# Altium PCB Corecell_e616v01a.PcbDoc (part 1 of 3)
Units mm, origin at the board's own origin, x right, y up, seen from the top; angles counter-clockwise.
Board outline 72.95 x 30.9 mm, 4 copper layers (Top Layer, MidLayer1 - GND, MidLayer2, Bottom Layer), stack 0.637 mm thick; 233 components, 174 nets, 666 pads, 1160 vias.
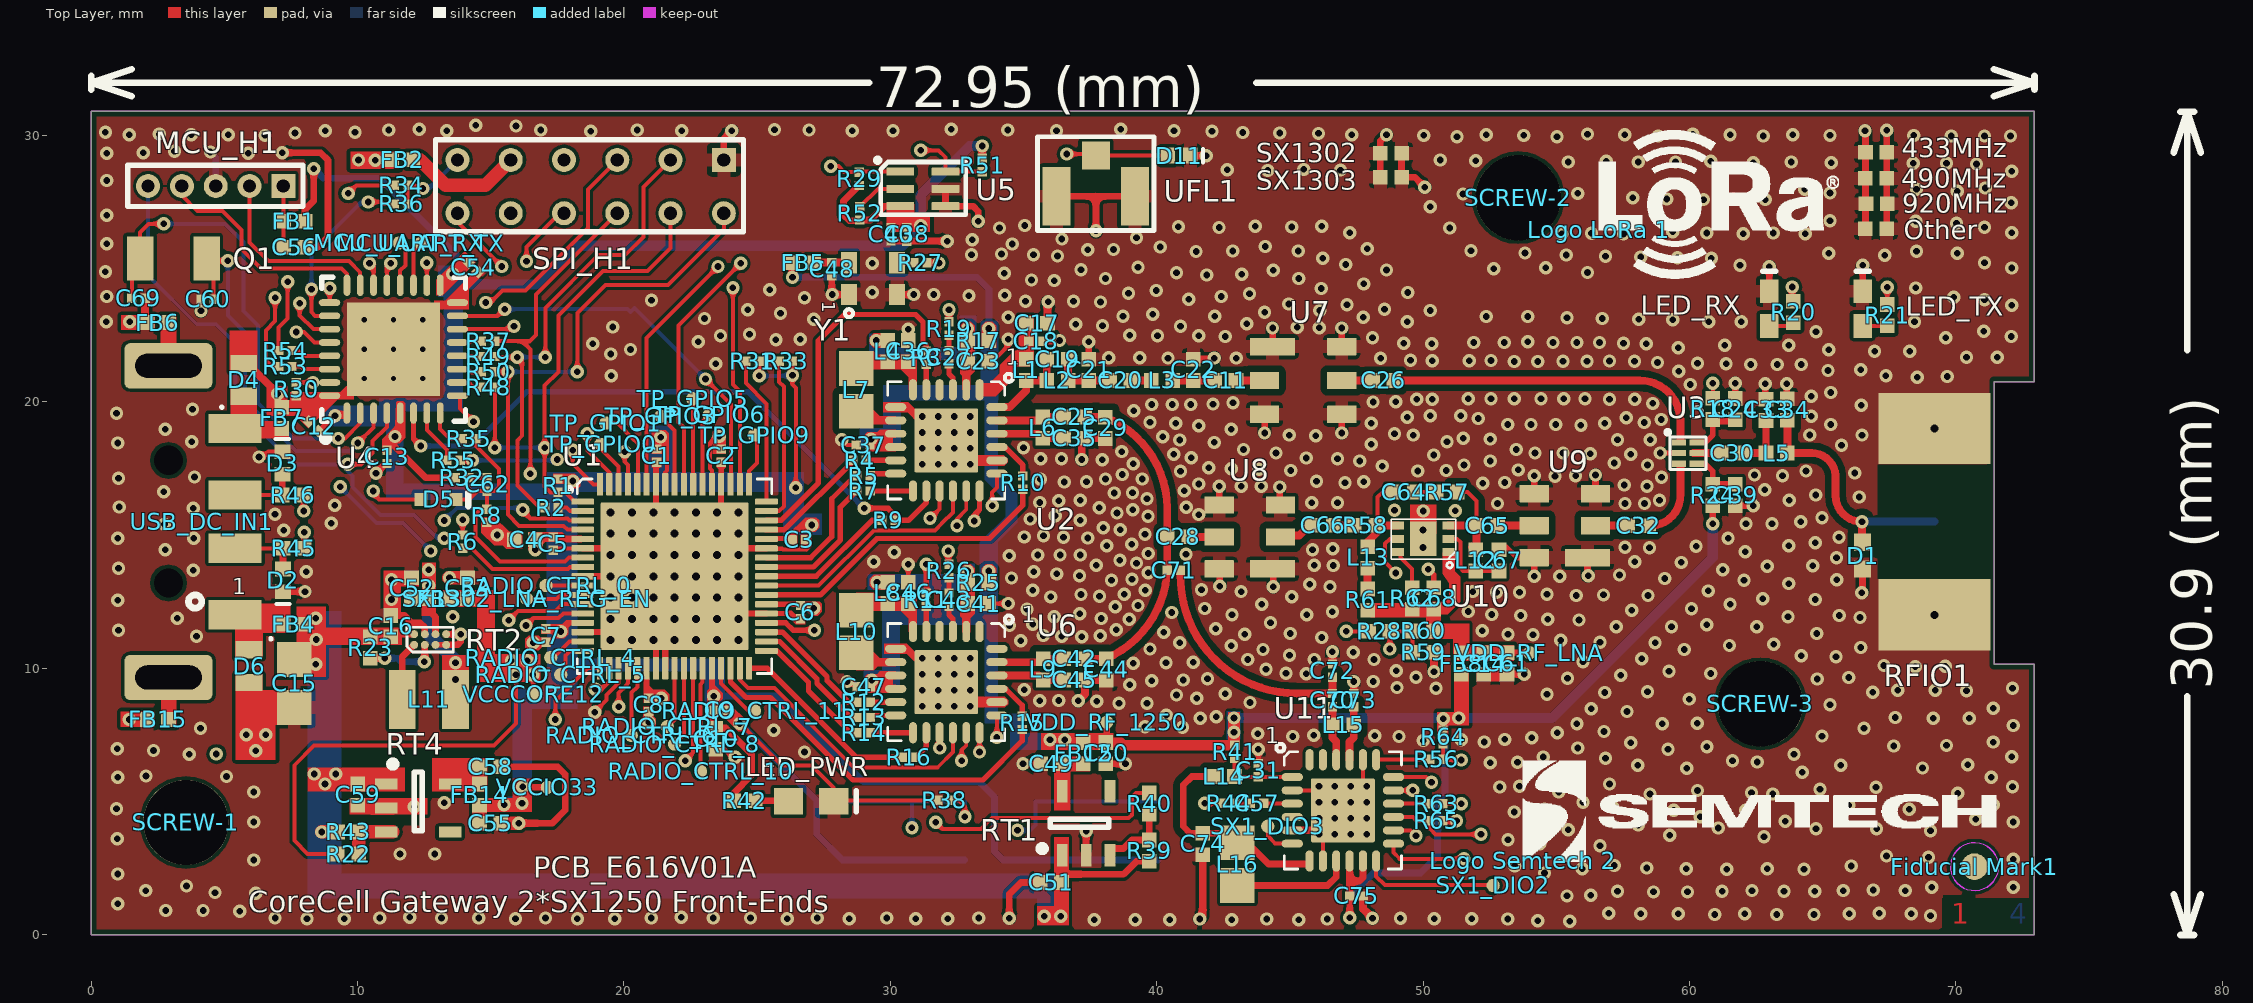
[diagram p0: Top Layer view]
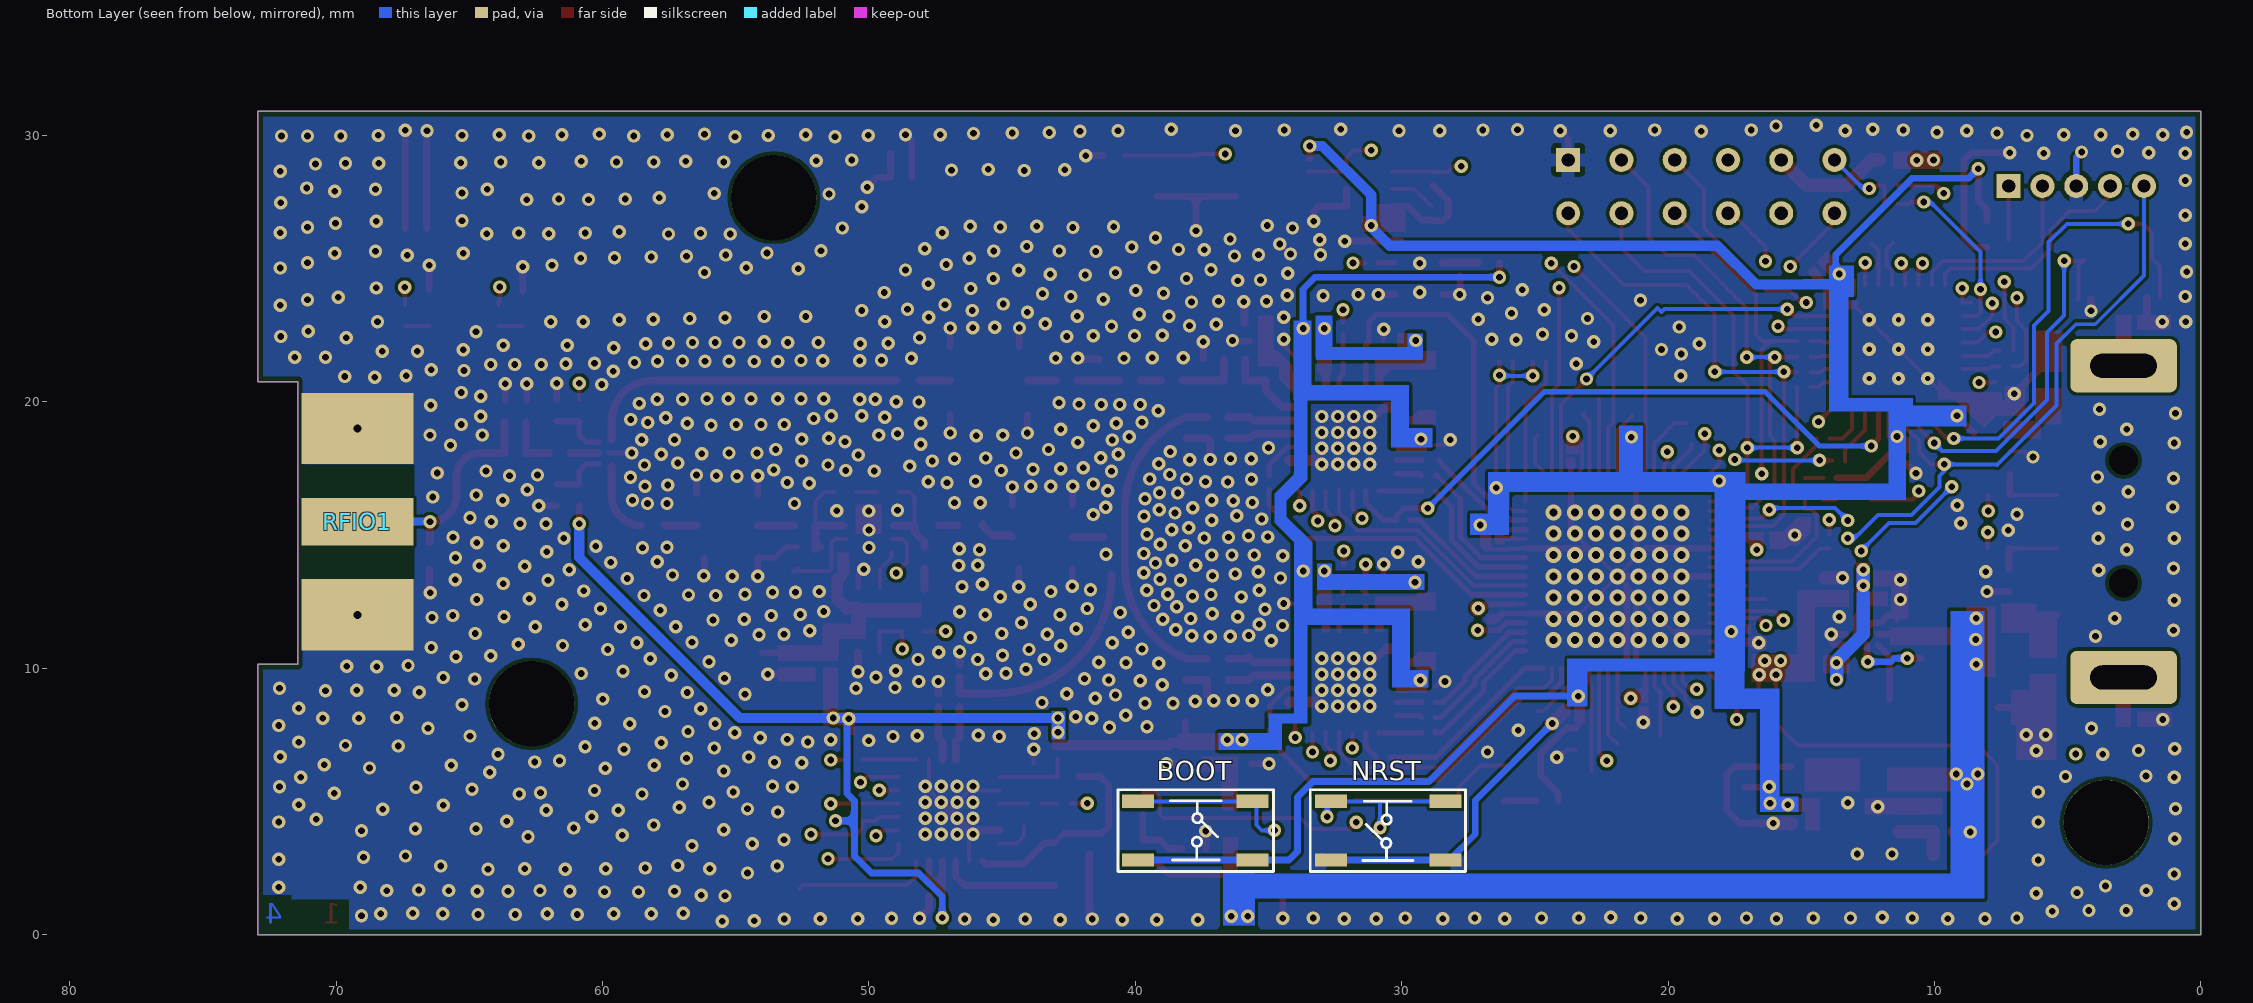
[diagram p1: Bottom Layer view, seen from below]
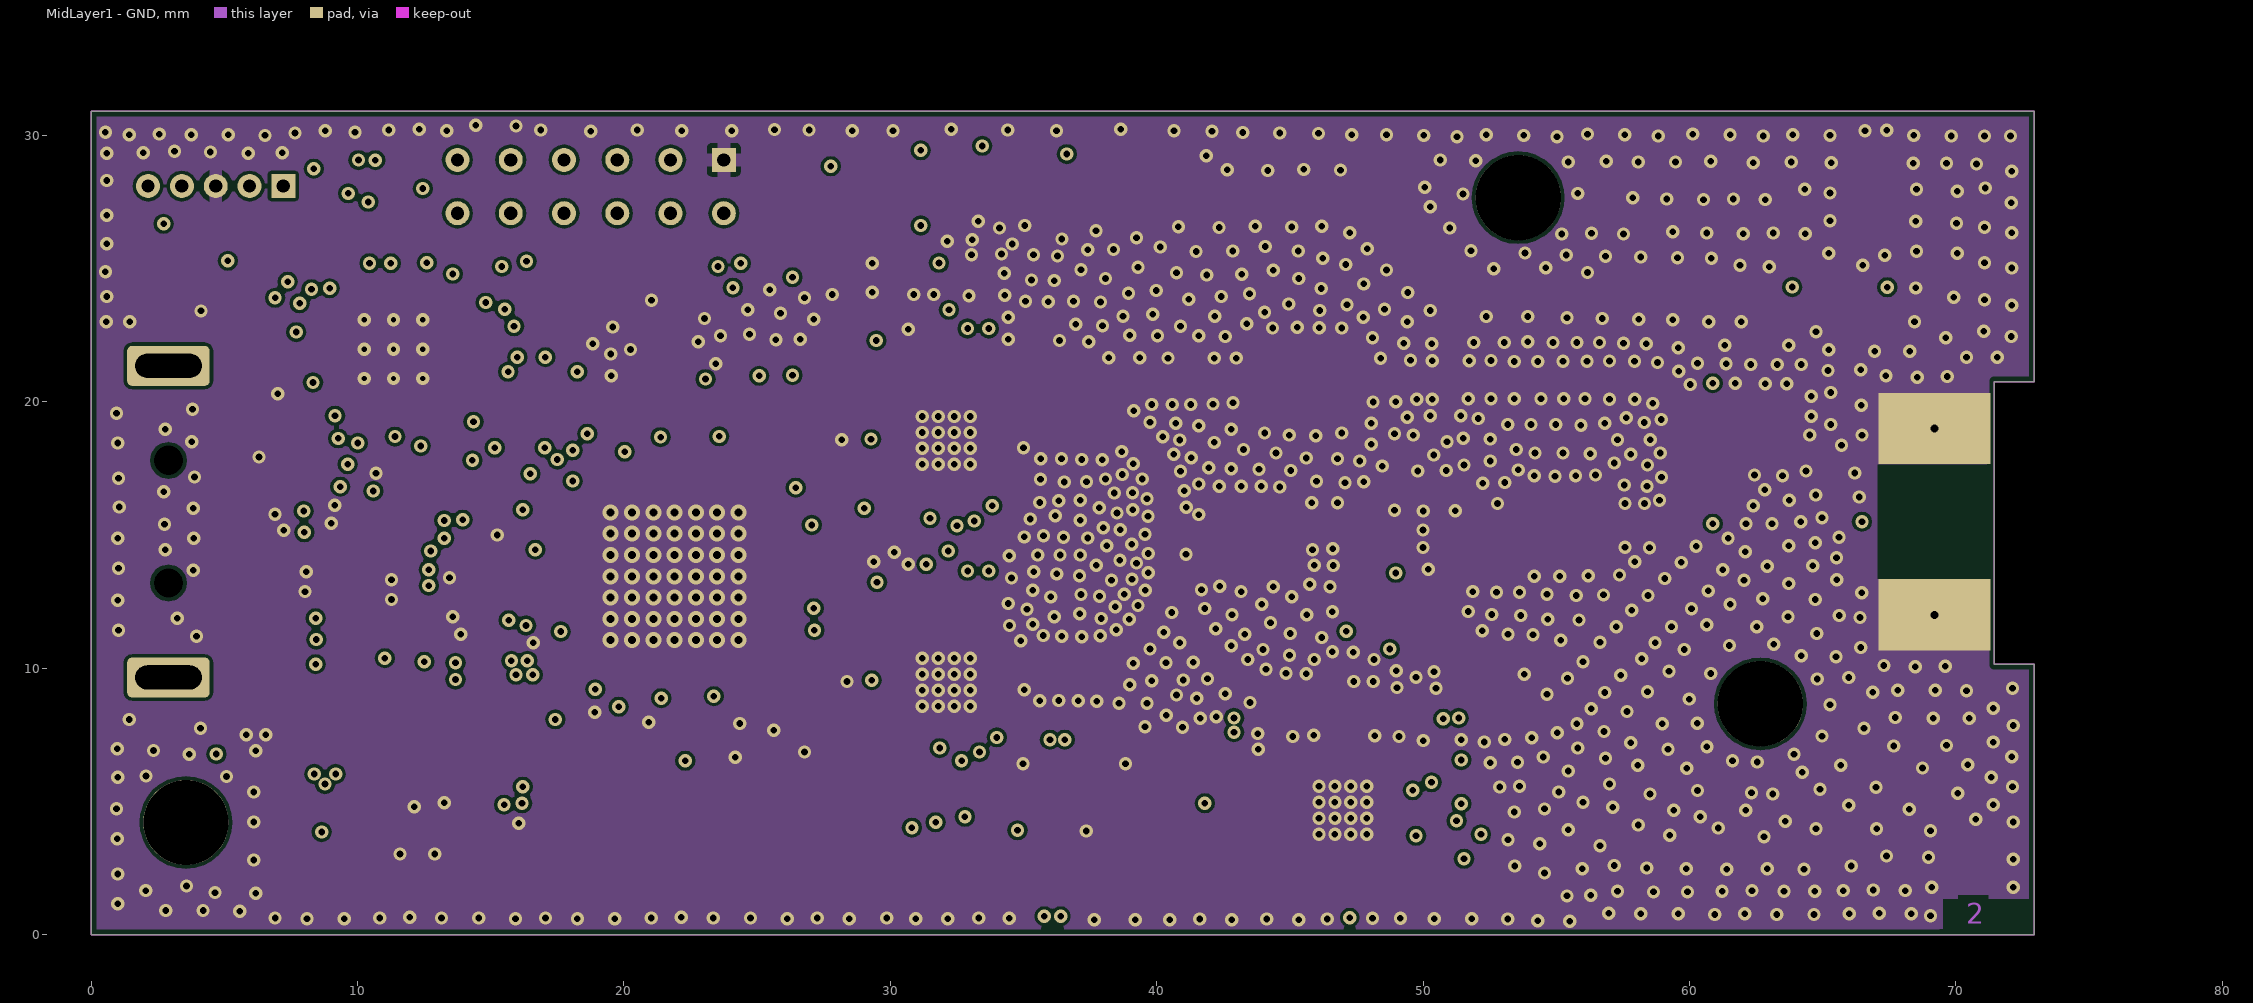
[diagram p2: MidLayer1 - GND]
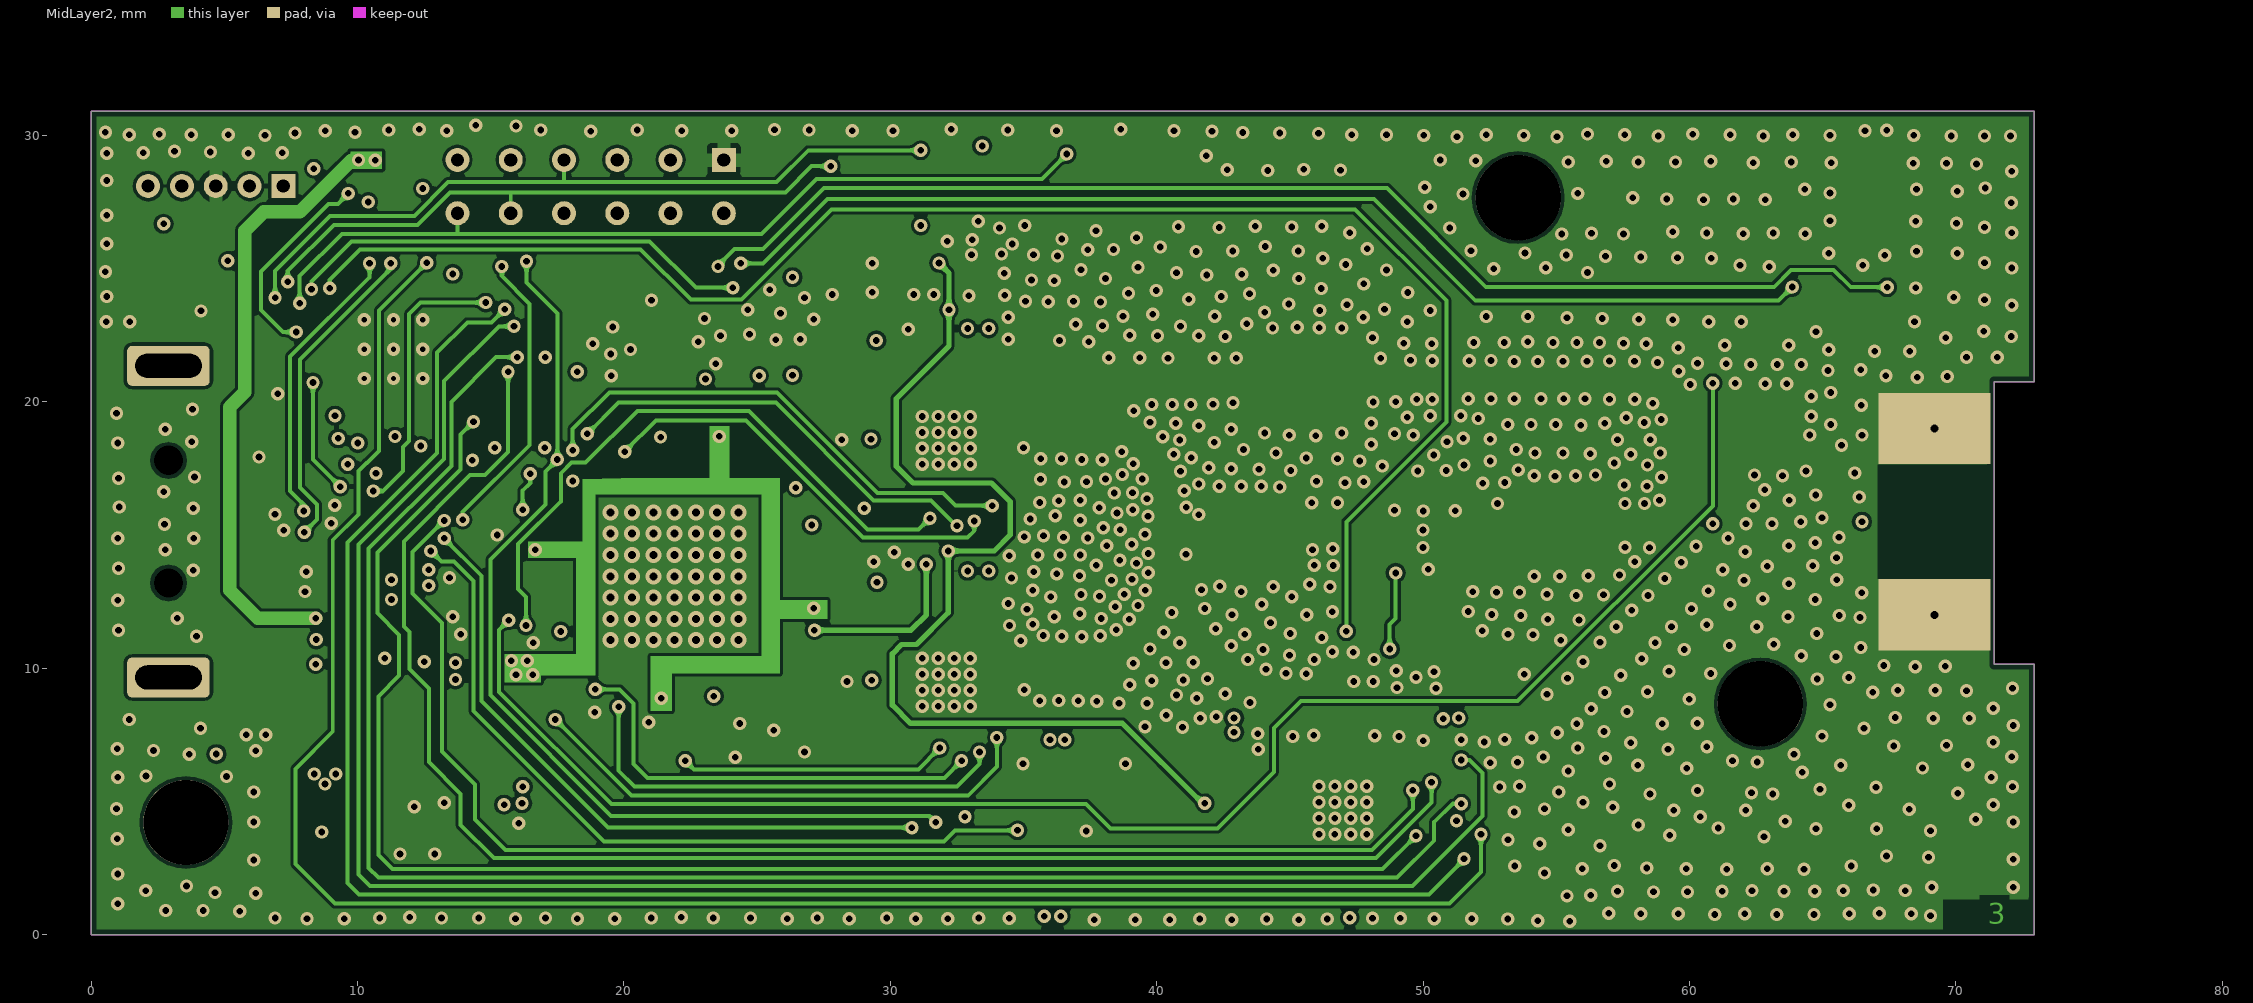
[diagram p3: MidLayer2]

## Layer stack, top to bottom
Top Solder: solder mask 0.0102, Solder Resist, Dk 3.5
Top Layer: signal copper 0.035
Dielectric1: core 0.15, FR-4, Dk 4.3
MidLayer1 - GND: signal copper 0.018
Dielectric 5: prepreg 0.127, Dk 4.2
MidLayer2: signal copper 0.018
Dielectric2: core 0.254, FR-4, Dk 4.2
Bottom Layer: signal copper 0.035
Bottom Solder: solder mask 0.0102, Solder Resist, Dk 3.5

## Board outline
0,0 0,30.9 72.95,30.9 72.95,20.75 71.45,20.75 71.45,10.15 72.95,10.15 72.95,0

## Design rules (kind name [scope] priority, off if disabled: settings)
BoardOutlineClearance [All] p1: gap=0.2 ignorepadtopadclearanceinfootprint=FALSE
Clearance Clearance_RF_Area_TOP [InNet('GND') And OnLayer('Top Layer') And (InPolygon) vs InNet('NetL8*') or InNet('NetC8*')  or  InNet('NetL9*') or InNet('NetC9*') or  InNet('NetL7*') or InNet('NetC7*')  or  InNet('NetU8*') or InNet('NetU9*') or InNet('NetU7*')  or  InNet('NetR8*') or InNet('NetR9*') or  InNet('NetR7*') or InNet('RF*')  or  InNet('NetU10*') or  InNet('NetC28*') or  InNet('NetC66*') or  InNet('NetC58*') or  InNet('NetC65*')   or  InNet('NetC32*') or  InNet('NetU3*') or  InNet('NetC42*') or  InNet('NetC44*')  or  InNet('NetC29*') or  InNet('NetC25*')  or  InNet('NetC30*')  or  InNet('NetL5*')  or  InNet('NetC34*')or  InNet('NetC26*')  or  InNet('NetC11*')   or  InNet('NetL3*') or  InNet('NetC20*')  or  InNet('NetL2*')       or  InNet('NetC19*')] p1: gap=0.25 ignorepadtopadclearanceinfootprint=FALSE except(0.15: Arc-Arc Arc-Track Track-Track)
Clearance Clearance_DC_Supply [((InPolygon) and ( InNet('VCCIO33') or InNet('VCCCORE12') or InNet('VCC_FEM') or InNet('VCC_FEM_1') or InNet('VCC_REG_IN') or  InNet('VDD_RF_125x') or  InNet('VDD_RF_126x') or InNet('VCC5V_IN') or  InNet('VCC5V')))  AND InComponentClass('SX1302_e520v01a_Power&Interface')] p2: gap=0.15 ignorepadtopadclearanceinfootprint=FALSE
Clearance Clearance_GND [InNet('GND')] p3: gap=0.12 ignorepadtopadclearanceinfootprint=FALSE
Clearance "Clearance ALL" [All] p4: gap=0.12 ignorepadtopadclearanceinfootprint=FALSE
ComponentClearance "Component Test Pin" [HasFootprint('PIN_SMD')] p1: gap=0.05 collisioncheckmode=3 verticalgap=0.2 showdistances=FALSE
ComponentClearance [All] p2: gap=0.2 collisioncheckmode=3 verticalgap=0.25 showdistances=FALSE
ComponentOrientations [All] p1: allowedrotations=32
DiffPairsRouting [All] p1: maxlimit=0.3 minlimit=0.15 mostfreqgap=0.2 toplayer_minwidth=0.15 toplayer_maxwidth=0.3 toplayer_prefwidth=0.2 midlayer1_minwidth=0.15 midlayer1_maxwidth=0.3 midlayer1_prefwidth=0.2 midlayer2_minwidth=0.15 midlayer2_maxwidth=0.3 midlayer2_prefwidth=0.2 bottomlayer_minwidth=0.15 bottomlayer_maxwidth=0.3 bottomlayer_prefwidth=0.2 maxuncoupledlength=12.7
HoleSize [All] p1: absolutevalues=TRUE maxlimit=6.5 minlimit=0.2 maxpercent=80.000 minpercent=20.000
HoleToHoleClearance [All] p1: gap=0.2 allowstackedmicrovias=TRUE
Length [All] p1: maxlimit=400 minlimit=0
MinimumAnnularRing [All] p1: minimumring=0.1
MinimumSolderMaskSliver [All] p1: minsoldermaskwidth=0.05
NetsToIgnore [All] p1:
OvershootFalling [All] p1: maximum=1.000
PermittedLayers [All] p1: toplayerpermitted=TRUE bottomlayerpermitted=TRUE
PlaneClearance [All] p1: clearance=0.2
PlaneConnect [All] p1: planeconnectstyle=Direct reliefexpansion=0.2 reliefentries=4 reliefconductorwidth=0.3 reliefairgap=0.2
PolygonConnect PolygonConnect_Specific_RF [InNet('GND') vs HasFootprint('SKY66420_16P_3X3MM')  or  HasFootprint('SKY66423_16P_3X3MM')] p1: thpad.connectstyle=Direct thpad.reliefconductorwidth=0.254 thpad.reliefentries=4 thpad.polygonreliefangle="90 Angle" thpad.airgapwidth=0.254 smdpad.connectstyle=Relief smdpad.reliefconductorwidth=0.3 smdpad.reliefentries=4 smdpad.polygonreliefangle="90 Angle" smdpad.airgapwidth=0.127 via.connectstyle=Direct via.reliefconductorwidth=0.254 via.reliefentries=4 via.polygonreliefangle="90 Angle" via.airgapwidth=0.254
PolygonConnect "PolygonConnect DGND 0402 0201" [InNet('GND') vs HasFootprint('rlc_402_smd_small') or HasFootprint('rlc_402_smd') or  HasFootprint('rlc_201_smd_small')or HasFootprint('rlc_201_smd')] p2: thpad.connectstyle=Relief thpad.reliefconductorwidth=0.5 thpad.reliefentries=4 thpad.polygonreliefangle="90 Angle" thpad.airgapwidth=0.127 smdpad.connectstyle=Relief smdpad.reliefconductorwidth=0.5 smdpad.reliefentries=4 smdpad.polygonreliefangle="90 Angle" smdpad.airgapwidth=0.127 via.connectstyle=Direct via.reliefconductorwidth=0.5 via.reliefentries=4 via.polygonreliefangle="90 Angle" via.airgapwidth=0.2
PolygonConnect "PolygonConnect GND SMD" [InNet('GND') vs HasFootprint('rlc_603_smd') or HasFootprint('rlc_603_smd_small') or hasFootprint('rlc_805_smd') or  hasFootprint('rlc_805_smd_small') or  HasFootprint('L4818') or  HasFootprint('CD2012-0402') or HasFootprint('CD1608-0603') or  HasFootprint('VQFN68_7X7MM') or HasFootprint('MLPQ-W18') or HasFootprint('HWSON10_3.0X3.0MM') or  HasFootprint('VQFN32_5X5MM')   or  HasFootprint('TCXO 2.0X1.6MM') or HasFootprint('vqfn24_4x4mm')  or  HasFootprint('SLP1006P2T')  or HasFootprint('CD1608-0603')   or HasFootprint('CD3224') or HasFootprint('DFN6_3X3MM')  or  HasFootprint('SKY66423_16P_3X3MM') or  HasFootprint('SKY66420_16P_3X3MM') or  HasFootprint('CD1005-0402') or  HasFootprint('UDFN-6L_2X2mm')   or  HasFootprint('DCC6C_3.0X3.0MM') or HasFootprint('header_6_2_2.0') or HasFootprint('UFL') or  HasFootprint('DCC6C_3.8x3.8mm') or HasFootprint('ProgPad') or HasFootprint('UDFN-6L_2X2mm')] p3: thpad.connectstyle=Relief thpad.reliefconductorwidth=0.5 thpad.reliefentries=4 thpad.polygonreliefangle="90 Angle" thpad.airgapwidth=0.178 smdpad.connectstyle=Relief smdpad.reliefconductorwidth=0.5 smdpad.reliefentries=4 smdpad.polygonreliefangle="90 Angle" smdpad.airgapwidth=0.127 via.connectstyle=Direct via.reliefconductorwidth=0.5 via.reliefentries=4 via.polygonreliefangle="90 Angle" via.airgapwidth=0.2
PolygonConnect PolygonConnect_comp_diverse [InNet('GND') vs HasFootprint('pin_1mm') or  HasFootprint('pin_0.9mm')] p4: thpad.connectstyle=Relief thpad.reliefconductorwidth=0.5 thpad.reliefentries=4 thpad.polygonreliefangle="90 Angle" thpad.airgapwidth=0.127 smdpad.connectstyle=Relief smdpad.reliefconductorwidth=0.5 smdpad.reliefentries=4 smdpad.polygonreliefangle="90 Angle" smdpad.airgapwidth=0.127 via.connectstyle=Direct via.reliefconductorwidth=0.5 via.reliefentries=4 via.polygonreliefangle="90 Angle" via.airgapwidth=0.15
PolygonConnect PolygonConnect_all [All] p5: connectstyle=Direct reliefconductorwidth=0.6 reliefentries=4 polygonreliefangle="90 Angle" airgapwidth=0.127
RoutingVias [All] p1: holewidth=0.25 width=0.5 viastyle="Through Hole" minholewidth=0.2 minwidth=0.4 maxholewidth=0.3 maxwidth=0.6
SMDToCorner [All] p1: distance=7874
SilkToSilkClearance [All] p1: silktosilkclearance=0.05
SilkToSolderMaskClearance SilkscreenOverComponentPads [IsPad] p1: minsilkscreentomaskgap=0.05 clearancetoexposedcopper=TRUE
SolderMaskExpansion [All] p1: expansion=0.05
SupplyNets [All] p1: voltage=3.300
ViasUnderSMD [All] p1: allowed=TRUE
Width Width_10mil [All] p1 off: maxlimit=0.254 minlimit=0.254 preferedwidth=0.254
Width "Width GND" [InNet('GND')] p2 off: maxlimit=3 minlimit=0.2 preferedwidth=0.4
Width Width_VCC [InNet('VCCDIG33') or   InNet('VCCDIG18') or  InNet('+5V') or  InNet('VDD5V_USB') or  InNet('VCC_FEM')  or  InNet('VCC_FEM_1')] p3 off: maxlimit=4 minlimit=0.15 preferedwidth=0.8
Width "Width All" [All] p4: maxlimit=2 minlimit=0.1 preferedwidth=0.15
21 further rules are at their usual default settings.

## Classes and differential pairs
component class Corecell_e616v01a_RF_Part: C11 C17 C18 C19 C20 C21 C22 C23 C24 C25 C26 C27 C28 C29 C30 C31 C32 C33 C34 C35 C36 C37 C39 C41 C42 C43 C44 C45 C46 C47 C48 C57 C64 C65 C66 C67 C68 C70 C71 C72 C73 C74 C75 C828 C833 C836 C837 D1 FB5 L1 L2 L3 L4 L5 L6 L7 L8 L9 L10 L12 L13 L14 L15 L16 L811 L813 L814 R17 R18 R19 R24 R25 R26 R27 R28 R41 R44 R56 R57 R58 R59 R60 R61 R62 R63 R64 R65 R815 R914 RFIO1 RFIO_1 SX1_DIO2 SX1_DIO3 U2 U3 U6 U7 U8 U9 U10 U11 Y1
component class Corecell_e616v01a_MCU: 433MHz 490MHz 920MHz BOOT C12 C13 C38 C40 C54 C56 C60 C69 D11 FB1 "Fiducial Mark1" "Logo LoRa 1" "Logo Semtech 2" MCU_H1 MCU_UART_RX MCU_UART_TX NRST Other Q1 R29 R30 R34 R35 R36 R37 R38 R48 R49 R50 R51 R52 R53 R54 R55 SCREW-1 SCREW-2 SCREW-3 SPI_H1 U4 U5 UFL1
component class Corecell_e616v01a_Main_Part: C1 C2 C3 C4 C5 C6 C7 C8 C9 C10 C62 D5 LED_RX LED_TX R1 R2 R3 R4 R5 R6 R7 R8 R9 R10 R11 R12 R13 R14 R15 R16 R20 R21 R31 R32 R33 RADIO_CTRL_0 RADIO_CTRL_4 RADIO_CTRL_5 RADIO_CTRL_6 RADIO_CTRL_7 RADIO_CTRL_8 RADIO_CTRL_10 RADIO_CTRL_11 SX1302 SX1302_LNA_REG_EN SX1303 TP_GPIO0 TP_GPIO1 TP_GPIO3 TP_GPIO5 TP_GPIO6 TP_GPIO9 U1
component class Corecell_e616v01a_Power: C14 C15 C16 C49 C50 C51 C52 C53 C55 C58 C59 C61 D2 D3 D4 D6 FB2 FB3 FB4 FB6 FB7 FB8 FB12 FB14 FB15 L11 LED_PWR R22 R23 R39 R40 R42 R43 R45 R46 RT1 RT2 RT4 USB_DC_IN1 VCCCORE12 VCCIO33 VDD_RF_1250 VDD_RF_LNA

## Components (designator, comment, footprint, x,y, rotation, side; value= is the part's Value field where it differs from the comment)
433MHz "Resistor" rlc_402_smd_small 67.008,29.367 r180 top value=NC
490MHz "Resistor" rlc_402_smd_small 67,28.388 r180 top value=0R
920MHz "Resistor" rlc_402_smd_small 67.025,27.432 r180 top value=NC
BOOT "SPST Switch" TACKLE_3*3MM 37.75,3.9 r0 bottom locked value=SW_3_3_1.5
C1 "Cap" rlc_201_smd_small 21.225,17.975 r90 top value=100nF
C2 "Cap" rlc_201_smd_small 23.65,17.975 r90 top value=100nF
C3 "Cap" rlc_201_smd_small 26.575,14.825 r180 top value=100nF
C4 "Cap" rlc_402_smd_small 16.275,14.825 r0 top value=1uF
C5 "Cap" rlc_201_smd_small 17.35,14.675 r90 top value=100nF
C6 "Cap" rlc_201_smd_small 26.625,12.1 r90 top value=100nF
C7 "Cap" rlc_201_smd_small 17.075,11.225 r90 top value=100nF
C8 "Cap" rlc_201_smd_small 20.925,8.625 r90 top value=100nF
C9 "Cap" rlc_201_smd_small 23.6,8.425 r180 top value=100nF
C10 "Cap" rlc_402_smd_small 23.45,7.35 r90 top value=1uF
C11 "Cap" rlc_402_smd_small 42.575,20.8 r0 top value=100pF
C12 "Cap" rlc_201_smd_small 8.35,19.075 r315 top value=100nF
C13 "Cap" rlc_201_smd_small 11.104,17.932 r90 top value=100nF
C14 "Cap" rlc_402_smd_small 52.273,10.169 r90 top value=100nF
C15 "Cap" rlc_805_smd 7.625,9.425 r270 top value=1uF
C16 "Cap" rlc_402_smd_small 11.25,11.575 r90 top value=10uF
C17 "Cap" rlc_402_smd_small 35.5,22.95 r180 top value=47nF
C18 "Cap" rlc_201_smd_small 35.45,22.275 r180 top value=82pF
C19 "Cap" rlc_402_smd_small 36.275,21.6 r180 top value=3.6pF
C20 "Cap" rlc_402_smd_small 38.625,20.8 r180 top value=100pF
C21 "Cap" rlc_402_smd_small 37.45,21.2 r270 top value=12pF
C22 "Cap" rlc_402_smd_small 41.375,21.2 r270 top value=8.2pF
C23 "Cap" rlc_402_smd_small 33.3,21.525 r180 top value=1uF
C24 "Cap" rlc_402_smd_small 61.725,19.725 r270 top value=100pF
C25 "Cap" rlc_402_smd_small 36.903,19.431 r180 top value=100pF
C26 "Cap" rlc_402_smd_small 48.5,20.8 r0 top value=100pF
C27 "Cap" rlc_201_smd_small 32.2,21.675 r90 top value=10pF
C28 "Cap" rlc_402_smd_small 40.798,14.927 r0 top value=100pF
C29 "Cap" rlc_402_smd_small 38.075,19.025 r90 top value=NC
C30 "Cap" rlc_402_smd_small 61.6,18.077 r0 top value=100pF
C31 "Cap" rlc_201_smd_small 43.815,6.172 r270 top value=10nF
C32 "Cap" rlc_402_smd_small 58.075,15.35 r0 top value=100pF
C33 "Cap" rlc_402_smd_small 62.875,19.7 r90 top value=NC
C34 "Cap" rlc_402_smd_small 63.675,19.71 r90 top value=NC
C35 "Cap" rlc_402_smd_small 36.903,18.631 r180 top value=100pF
C36 "Cap" rlc_402_smd_small 30.675,21.9 r270 top value=470nF
C37 "Cap" rlc_201_smd_small 28.975,18.375 r0 top value=100nF
C38 "Cap" rlc_201_smd_small 30.622,26.282 r270 top value=2.2uF
C39 "Cap" rlc_402_smd_small 61.725,16.5 r270 top value=100pF
C40 "Cap" rlc_201_smd_small 30.022,26.289 r270 top value=100nF
C41 "Cap" rlc_402_smd_small 33.3,12.425 r180 top value=1uF
C42 "Cap" rlc_402_smd_small 36.91,10.357 r180 top value=100pF
C43 "Cap" rlc_201_smd_small 32.2,12.575 r90 top value=10pF
C44 "Cap" rlc_402_smd_small 38.1,9.95 r90 top value=NC
C45 "Cap" rlc_402_smd_small 36.91,9.557 r180 top value=100pF
C46 "Cap" rlc_402_smd_small 30.675,12.825 r270 top value=470nF
C47 "Cap" rlc_201_smd_small 29,9.3 r0 top value=100nF
C48 "Cap" rlc_201_smd_small 27.8,24.975 r90 top value=100nF
C49 "Cap" rlc_402_smd_small 36.043,6.409 r180 top value=4.7uF
C50 "Cap" rlc_402_smd_small 38.09,6.809 r90 top value=100nF
C51 "Cap" rlc_402_smd_small 36.028,1.956 r180 top value=1uF
C52 "Cap" rlc_402_smd_small 12.025,13 r270 top value=10uF
C53 "Cap" rlc_402_smd_small 14.125,13 r270 top value=100nF
C54 "Cap" rlc_201_smd_small 14.35,25.05 r135 top value=100nF
C55 "Cap" rlc_402_smd_small 14.975,4.175 r180 top value=100nF
C56 "Cap" rlc_402_smd_small 7.625,25.8 r180 top value=100nF
C57 "Cap" rlc_201_smd_small 43.764,4.928 r180 top value=10pF
C58 "Cap" rlc_402_smd_small 14.975,6.3 r0 top value=4.7uF
C59 "Cap" rlc_402_smd_small 10,5.25 r270 top value=1uF
C60 "Cap" rlc_201_smd_small 4.371,23.849 r180 top value=NC
C61 "Cap" rlc_402_smd_small 53.15,10.177 r90 top value=100nF
C62 "Cap" rlc_201_smd_small 14.859,16.895 r90 top value=100nF
C64 "Cap" rlc_402_smd_small 49.272,16.613 r180 top value=NC
C65 "Cap" rlc_402_smd_small 52.4,15.353 r180 top value=6.8pF
C66 "Cap" rlc_402_smd_small 46.232,15.367 r180 top value=100pF
C67 "Cap" rlc_402_smd_small 52.85,14.05 r270 top value=47pF
C68 "Cap" rlc_402_smd_small 50.398,12.615 r90 top value=47nF
C69 "Cap" rlc_201_smd_small 1.775,23.891 r180 top value=NC
C70 "Cap" rlc_201_smd_small 46.596,8.8 r270 top value=4.7pF
C71 "Cap" rlc_201_smd_small 40.64,13.675 r0 top value=4.7pF
C72 "Cap" rlc_201_smd_small 46.596,9.906 r270 top value=1pF
C73 "Cap" rlc_201_smd_small 47.396,8.8 r270 top value=3.9pF
C74 "Cap" rlc_402_smd_small 41.725,3.4 r90 top value=470nF
C75 "Cap" rlc_201_smd_small 47.498,1.448 r180 top value=100nF
D1 "RClamp1561PQ" SLP1006P2 66.497,14.224 r270 top
D2 "RClamp0531" SLP1006P2T 7.2,13.3 r270 top
D3 "RClamp0531" SLP1006P2T 7.175,17.7 r90 top
D4 "uClamp0571" 1610 5.725,20.825 r90 top
D5 "D Schottky" SOD523 12.38,16.332 r0 top
D6 "uClamp0571" 1610 5.925,10.075 r270 top
D11 "RClamp0531" SLP1006P2T 40.839,29.242 r0 top
FB1 "Ferrite beads" rlc_402_smd_small 7.625,26.775 r0 top value="10R @100MHz"
FB2 "Ferrite beads" rlc_402_smd_small 11.675,29.087 r0 top value=NC
FB3 "Ferrite beads" rlc_402_smd_small 13.075,12.6 r0 top value="10R @100MHz"
FB4 "Ferrite beads" rlc_402_smd_small 7.6,11.65 r0 top value="10R @100MHz"
FB5 "Ferrite beads" rlc_402_smd_small 26.725,25.225 r0 top value="10R @100MHz"
FB6 "Ferrite beads" rlc_402_smd_small 2.5,22.975 r0 top value="10R @100MHz"
FB7 "Ferrite beads" rlc_402_smd_small 7.15,19.4 r90 top value="10R @100MHz"
FB8 "Ferrite beads" rlc_402_smd_small 51.435,10.175 r270 top value="10R @100MHz"
FB12 "Ferrite beads" rlc_402_smd_small 37.24,6.809 r90 top value="10R @100MHz"
FB14 "Ferrite beads" rlc_402_smd_small 14.575,5.25 r270 top value="10R @100MHz"
FB15 "Ferrite beads" rlc_402_smd_small 2.5,8.075 r0 top value="10R @100MHz"
"Fiducial Mark1" "Logo symbol  BOT" fiducial_mark_signal_top 70.7,2.55 r90 top
L1 "Inductor" rlc_402_smd_small 35.1,21.2 r90 top value=56nH
L2 "Inductor" rlc_402_smd_small 36.275,20.8 r0 top value=8.2nH
L3 "Inductor" rlc_402_smd_small 40.2,20.8 r0 top value=18nH
L4 "Inductor" rlc_402_smd_small 29.9,21.9 r270 top value=NC
L5 "Inductor" rlc_402_smd_small 63.275,18.075 r0 top value=0R
L6 "Inductor" rlc_402_smd_small 35.725,19.031 r90 top value=NC
L7 "Inductor" rlc_805_smd_small 28.725,20.45 r270 top value=15uH
L8 "Inductor" rlc_402_smd_small 29.9,12.825 r270 top value=NC
L9 "Inductor" rlc_402_smd_small 35.738,9.957 r90 top value=NC
L10 "Inductor" rlc_805_smd_small 28.725,11.375 r270 top value=15uH
L11 "Inductor" 2520 12.675,8.825 r0 top value=2.2uH
L12 "Inductor" rlc_402_smd_small 51.975,14.05 r90 top value=27nH
L13 "Inductor" rlc_402_smd_small 47.917,14.157 r90 top value=100nH
L14 "Inductor" rlc_402_smd_small 42.52,5.935 r180 top value=47nH
L15 "Inductor" rlc_402_smd_small 46.996,7.874 r180 top value=33nH
L16 "Inductor" rlc_805_smd_small 43.028,2.642 r270 top value=15uH
LED_PWR "LED" CD1608-0603 27.025,5 r0 top value=Red_0603
LED_RX "RX_LED" CD1005-0402 63,23.5 r90 top locked value=GREEN_0402
LED_TX "TX_LED" CD1005-0402 66.5,23.5 r90 top locked value=RED_0402
"Logo LoRa 1" "Logo symbol Bot" "LOGO LORA SIZE2" 56.591,26.467 r0 top
"Logo Semtech 2" "Logo Semtech  Bot2" logo_semtech_horiz_size2 53.746,2.769 r0 top
MCU_H1 "Header 5" ProgPad 4.675,28.1 r180 top value=NC
MCU_UART_RX "Test Pin" PIN_SMD#1 11.562,25.963 r90 top
MCU_UART_TX "Test Pin" PIN_SMD#1 12.375,25.95 r90 top
NRST "SPST Switch" TACKLE_3*3MM 30.5,3.9 r180 bottom value=SW_3_3_1.5
Other "Resistor" rlc_402_smd_small 67,26.497 r180 top value=NC
Q1 "3215" XTAL_3215_SMD 3.085,25.386 r180 top value=32.768kHz
R1 "Resistor" rlc_201_smd_small 17.525,16.85 r90 top value=10k
R2 "Resistor" rlc_201_smd_small 17.275,16.025 r180 top value=1k
R3 "Resistor" rlc_201_smd_small 31.35,21.65 r270 top value=0R
R4 "Resistor" rlc_201_smd_small 28.85,17.8 r0 top value=0R
R5 "Resistor" rlc_201_smd_small 29,17.225 r0 top value=0R
R6 "Resistor" rlc_201_smd_small 13.945,14.747 r270 top value=0R
R7 "Resistor" rlc_201_smd_small 29,16.65 r0 top value=0R
R8 "Resistor" rlc_201_smd_small 14.85,15.719 r90 top value=10k
R9 "Resistor" rlc_201_smd_small 29.925,15.55 r0 top value=0R
R10 "Resistor" rlc_201_smd_small 34.976,16.967 r90 top value=0R
R11 "Resistor" rlc_201_smd_small 31.35,12.575 r270 top value=0R
R12 "Resistor" rlc_201_smd_small 29,8.725 r0 top value=0R
R13 "Resistor" rlc_201_smd_small 29,8.15 r0 top value=0R
R14 "Resistor" rlc_201_smd_small 29,7.575 r0 top value=0R
R15 "Resistor" rlc_201_smd_small 34.95,7.95 r270 top value=0R
R16 "Resistor" rlc_201_smd_small 30.7,6.65 r180 top value=0R
R17 "Resistor" rlc_402_smd_small 33.3,22.3 r180 top value=0R
R18 "Resistor" rlc_402_smd_small 60.875,19.736 r90 top value=62k
R19 "Resistor" rlc_201_smd_small 32.2,22.75 r90 top value=220R
R20 "Resistor" rlc_402_smd_small 63.9,23.368 r270 top value=680R
R21 "Resistor" rlc_402_smd_small 67.425,23.25 r90 top value=680R
R22 "Resistor" rlc_402_smd_small 9.643,3.023 r180 top value=10k
R23 "Resistor" rlc_402_smd_small 10.475,10.775 r270 top value=10k
R24 "Resistor" rlc_402_smd_small 60.875,16.5 r270 top value=10k
R25 "Resistor" rlc_402_smd_small 33.3,13.2 r180 top value=0R
R26 "Resistor" rlc_201_smd_small 32.2,13.65 r90 top value=220R
R27 "Resistor" rlc_201_smd_small 31.125,25.225 r180 top value=0R
R28 "Resistor" rlc_402_smd_small 48.353,11.382 r180 top value=NC
R29 "Resistor" rlc_201_smd_small 28.831,28.372 r270 top value=4.7k
R30 "Resistor" rlc_201_smd_small 7.7,20.475 r90 top value=10k
R31 "Resistor" rlc_201_smd_small 24.825,21.525 r0 top value=4.7k
R32 "Resistor" rlc_201_smd_small 13.919,17.145 r180 top value=10R
R33 "Resistor" rlc_201_smd_small 26.075,21.525 r0 top value=4.7k
R34 "Resistor" rlc_201_smd_small 11.633,28.127 r180 top value=0R
R35 "Resistor" rlc_201_smd_small 14.18,18.618 r0 top value=0R
R36 "Resistor" rlc_201_smd_small 11.634,27.426 r180 top value=NC
R37 "Resistor" rlc_201_smd_small 14.9,22.275 r180 top value=0R
R38 "Resistor" rlc_201_smd_small 32.029,5.037 r180 top value=10k
R39 "Resistor" rlc_402_smd_small 39.717,3.15 r90 top value=NC
R40 "Resistor" rlc_402_smd_small 39.717,4.912 r90 top value=0R
R41 "Resistor" rlc_201_smd_small 42.926,6.858 r270 top value=NC
R42 "Resistor" rlc_402_smd_small 24.525,5.025 r0 top value=150R
R43 "Resistor" rlc_402_smd_small 9.65,3.85 r0 top value=NC
R44 "Resistor" rlc_201_smd_small 42.697,4.928 r180 top value=220R
R45 "Resistor" rlc_402_smd_small 7.6,14.5 r0 top value=0R
R46 "Resistor" rlc_402_smd_small 7.575,16.5 r0 top value=0R
R48 "Resistor" rlc_201_smd_small 14.9,20.55 r0 top value=0R
R49 "Resistor" rlc_201_smd_small 14.9,21.7 r180 top value=0R
R50 "Resistor" rlc_201_smd_small 14.9,21.125 r0 top value=0R
R51 "Resistor" rlc_201_smd_small 33.447,28.888 r90 top value=4.7k
R52 "Resistor" rlc_201_smd_small 28.854,27.075 r270 top value=10k
R53 "Resistor" rlc_201_smd_small 7.29,21.325 r180 top value=0R
R54 "Resistor" rlc_201_smd_small 7.29,21.925 r180 top value=0R
R55 "Resistor" rlc_201_smd_small 13.6,17.8 r0 top value=0R
R56 "Resistor" rlc_201_smd_small 50.495,6.579 r0 top value=0R
R57 "Resistor" rlc_402_smd_small 50.884,16.613 r180 top value=NC
R58 "Resistor" rlc_402_smd_small 47.822,15.367 r180 top value=15R
R59 "Resistor" rlc_402_smd_small 50.011,10.6 r0 top value=NC
R60 "Resistor" rlc_402_smd_small 49.997,11.396 r0 top value=0R
R61 "Resistor" rlc_402_smd_small 47.917,12.573 r270 top value=56R
R62 "Resistor" rlc_402_smd_small 49.589,12.615 r270 top value=1k
R63 "Resistor" rlc_201_smd_small 50.5,4.912 r0 top value=100R
R64 "Resistor" rlc_201_smd_small 50.75,7.417 r270 top value=10k
R65 "Resistor" rlc_201_smd_small 50.5,4.267 r180 top value=10k
RADIO_CTRL_0 "Test Pin" PIN_SMD#1 17.075,13.1 r90 top
RADIO_CTRL_4 "Test Pin" PIN_SMD#1 17.25,10.4 r90 top
RADIO_CTRL_5 "Test Pin" PIN_SMD#2 17.625,9.75 r180 top
RADIO_CTRL_6 "Test Pin" PIN_SMD#2 20.275,7.475 r90 top
RADIO_CTRL_7 "Test Pin" PIN_SMD#2 21.625,7.8 r90 top
RADIO_CTRL_8 "Test Pin" PIN_SMD#2 21.9,7.15 r180 top
RADIO_CTRL_10 "Test Pin" PIN_SMD#2 22.875,6.125 r180 top
RADIO_CTRL_11 "Test Pin" PIN_SMD#2 24.9,8.4 r180 top
RFIO1 "SMA" SMA_END_LAUNCH_1.6MM_6.35MM 69.2,15.5 r0 bottom locked value=SMA-KE11
RT1 "RT9078-3.3" TSOT-23-5 37.349,4.179 r90 top
RT2 "RT5707" CSP_8 12.725,11.075 r90 top value=RT5707-1.2
RT4 "RT9078-3.3" TSOT-23-5 12.275,4.75 r0 top
SCREW-1 "Logo symbol" SCREW-M3 3.556,4.208 r90 top
SCREW-2 "Logo symbol" SCREW-M3 53.569,27.661 r90 top
SCREW-3 "Logo symbol" SCREW-M3 62.662,8.661 r90 top
SPI_H1 "Header 6X2" header_6_2_2.0 18.75,28.08 r180 top value=NC
SX1_DIO2 "Test Pin" PIN_SMD#1 52.629,1.842 r90 top
SX1_DIO3 "Test Pin" PIN_SMD#1 44.171,4.064 r90 top
SX1302 "Resistor" rlc_402_smd_small 48.793,29.325 r180 top value=SX1302
SX1302_LNA_REG_EN "Test Pin" PIN_SMD#1 16.35,12.6 r90 top
SX1303 "Resistor" rlc_402_smd_small 48.798,28.432 r180 top value=NC
TP_GPIO0 "Test Pin" PIN_SMD#2 19.125,18.4 r90 top
TP_GPIO1 "Test Pin" PIN_SMD#1 19.325,19.2 r90 top
TP_GPIO3 "Test Pin" PIN_SMD#1 21.387,19.456 r90 top
TP_GPIO5 "Test Pin" PIN_SMD#1 22.581,20.11 r90 top
TP_GPIO6 "Test Pin" PIN_SMD#2 23.2,19.507 r90 top
TP_GPIO9 "Test Pin" PIN_SMD#3 24.9,18.725 r90 top
U1 "SX1303" VQFN68_7X7MM 21.9,13.45 r0 top
U2 "SX1250" VQFN24_4X4MM 32.1,18.55 r270 top locked
U3 "MXD8621C" DFN_6 59.942,18.075 r0 top
U4 "STM32L412Kx" UFQFPN32_5x5mm 11.35,21.975 r90 top value=STM32L412KBU6
U5 "STTS751-0DP3F" UDFN-6L_2X2mm 31.222,27.993 r0 top
U6 "SX1250" VQFN24_4X4MM 32.1,9.475 r270 top locked
U7 "SAW Filter" DCC6C_3.8x3.8mm 44.05,19.53 r0 top value=HDF500E5_s4
U8 "SAW Filter" DCC6C_3.0x3.0mm 43.498,14.927 r180 top value="HDF480e1_s6(use 0R 0603)"
U9 "SAW Filter" DCC6C_3.0x3.0mm 55.325,15.35 r180 top value=HDF480e1_s6
U10 "BGB707L7ESD" TSLP-7-1 50.009,14.856 r180 top value=BGB719N7ESD
U11 "SX1261" vqfn24_4x4mm 46.99,4.662 r0 top
UFL1 "UFL" UFL 37.713,28.479 r180 top
USB_DC_IN1 "USB Type-A SMD" "Keystone USB Type 931" 0,15.5 r0 top locked value="USB Type_A"
VCCCORE12 "Test Pin" PIN_SMD#1 16.6,9.018 r90 top
VCCIO33 "Test Pin" PIN_SMD#1 17.125,5.525 r90 top
VDD_RF_1250 "Test Pin" PIN_SMD#1 38.125,7.976 r90 top
VDD_RF_LNA "Test Pin" PIN_SMD#1 54,10.577 r90 top
Y1 "TCXO" "TCXO 2.0x1.6mm" 29.35,24.625 r0 top value=32.0MHz

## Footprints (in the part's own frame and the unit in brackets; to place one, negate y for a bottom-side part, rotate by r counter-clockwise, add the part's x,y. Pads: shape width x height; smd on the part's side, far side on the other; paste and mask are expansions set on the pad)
1610 [mm] "DFN, 2-Leads, Body 1.00x1.60mm, Pitch 1.10mm, IPC Low Density"
  rect 0.65x1 smd: 1(-0.613,0) 2(0.613,0)
  silkscreen extent -1.08,0.77 -0.98,0.87, body extent -0.82,-0.53 0.82,0.53, height 0.55
2520 [mm] "for 1239AS-H-2R2M,INDUCTOR"
  rect 1x2.2 smd paste+0 mask+0.05: 1(-1,0) 2(1,0)
CD1005-0402 [mm] "Chip Diode; Body 1.0 x 0.5 mm (LxW typ)"
  rect 0.9x0.7 smd mask+0.05: 1(-0.65,0) 2(0.65,0)
  silkscreen extent 1.4,-0.25 1.4,0.25
CD1608-0603 [mm] "Chip Diode; Body 1.6 x 0.8 mm (LxW typ)"
  rect 1.1x1 smd mask+0.05: 1(-0.85,0) 2(0.85,0)
  silkscreen extent 1.7,-0.4 1.7,0.4
CSP_8 [mm] "for RT5707,LDO"
  round 0.3 smd: A1(-0.2,0.6) A2(0.2,0.6) B1(-0.2,0.2) B2(0.2,0.2) C1(-0.2,-0.2) C2(0.2,-0.2) D1(-0.2,-0.6) D2(0.2,-0.6)
  silkscreen extent -0.47,-0.87 0.46,0.87
DCC6C_3.0x3.0mm [mm] "DCC6C footprint, 3.0x3.0mm optimized"
  rrect5% 1.7x0.65 smd paste+0 mask+0.05: 1(-0.85,1.2)
  rrect5% 1.1x0.65 smd paste+0 mask+0.05: 2(-1.15,0) 3(-1.15,-1.2) 4(1.15,-1.2) 5(1.15,0) 6(1.15,1.2)
  body extent -1.5,-1.5 1.5,1.5, height 1.1
DCC6C_3.8x3.8mm [mm] "DCC6C footprint, 3.8x3.8mm"
  rrect5% 1.7x0.65 smd paste+0 mask+0.05: 1(0.3,2.54)
  rrect5% 1.1x0.65 smd paste+0 mask+0.05: 2(0,1.27) 3(0,0) 4(2.9,0) 5(2.9,1.27) 6(2.9,2.54)
DFN_6 [mm] "for MXD8621C"
  rect 0.535x0.235 smd: 1(-0.332,0.4) 2(-0.332,0) 3(-0.332,-0.4) 4(0.333,-0.4) 5(0.333,0) 6(0.333,0.4)
  silkscreen extent -0.8,-0.62 0.68,0.82
fiducial_mark_signal_top [mm] "Fiducial mark for automatic assembly"
  round 1 smd paste-2 mask+0.5: 1(0,0)
  Top Layer keep-out circle w0.05: c0,0 r0.9
  body extent -0.9,-0.9 0.9,0.9, height 1
header_6_2_2.0 [mm] "2.0,header 6*2"
  rect 0.9x0.9 hole 0.5: 1(-5,-1)
  round 0.9 hole 0.5: 2(-5,1) 3(-3,-1) 4(-3,1) 5(-1,-1) 6(-1,1) 7(1,-1) 8(1,1) 9(3,-1) 10(3,1) 11(5,-1) 12(5,1)
  silkscreen extent -5.74,-1.75 5.83,1.7
"Keystone USB Type 931" [mm] "Connector Keystone; USB 2.0, Type A, SM; 4Position; Right Angle"
  rect 2x1.1 smd mask+0.05: 1(5.4,-3.5) 2(5.4,-1) 3(5.4,1) 4(5.4,3.5)
  rrect25% 3.3x1.7 / inner rrect25% 3.1x1.5 / far side rrect25% 4x2 hole 0.9 slot 2.5 at 0 deg paste-2 mask+0.05: 5(2.9,-5.85) 6(2.9,5.85)
  round 0 hole 1.1 unplated mask+0.05: NPTH1(2.9,2.3)
  round 0 hole 1.1 unplated paste+0 mask+0.05: NPTH2(2.9,-2.3)
  silkscreen extent 3.65,-3.25 4.15,-2.75, body extent 0.15,-6 6.45,6, height 0.8
"LOGO LORA SIZE2" [mm] "Logo LoRa Size2 - Top Overlay - 9x5.5mm - Registered"
  silkscreen extent 0,-1.83 9.02,3.72, body extent 1.83,-0.05 3.88,1.95, height 0.8
logo_semtech_horiz_size2 [mm] "Logo semtech horizontal - size2 - M"
  silkscreen extent 0,-0.03 17.78,3.76
PIN_SMD#1 [mm]
  round 0.5 smd paste-3 mask+0.025: 1(0,0)
PIN_SMD#2 [mm] "Generic Pin SMD; 1 Lead"
  round 0.5 smd paste-3 mask+0.05: 1(0,0)
PIN_SMD#3 [mm] "Generic Pin SMD; 1 Lead"
  round 0.5 smd paste-3 mask+0.05: 1(0.025,0)
ProgPad [mm] "1.27"
  rect 0.9x0.9 hole 0.5: 1(-2.54,0)
  round 0.9 hole 0.5: 2(-1.27,0) 3(0,0) 4(1.27,0) 5(2.54,0)
  silkscreen extent -3.28,-0.78 3.3,0.77
rlc_201_smd_small [mm] "Chip SMD component 201; Body 0.6 x 0.3 mm (LxW typ); small footprint"
  rect 0.35x0.35 smd paste+0 mask+0.025: 1(-0.25,0) 2(0.25,0)
  body extent -0.3,-0.15 0.3,0.15, height 0.5
rlc_402_smd_small [mm] "Chip SMD component 402; Body 1.0 x 0.5 mm (LxW typ);small footprint"
  rect 0.55x0.55 smd mask+0.025: 1(-0.4,0) 2(0.4,0)
  body extent -0.5,-0.25 0.5,0.25, height 0.6
rlc_805_smd [mm] "Chip SMD component 805; Body 2.0 x 1.25 mm (LxW typ)"
  rect 1.3x1.3 smd mask+0.05: 1(-0.9,0) 2(0.9,0)
  body extent -1,-0.63 1,0.63, height 1
rlc_805_smd_small [mm] "Chip SMD component 805; Body 2.0 x 1.25 mm (LxW typ); small footprint"
  rect 1.3x1.3 smd mask+0.05: 1(-0.8,0) 2(0.8,0)
  body extent -1,-0.63 1,0.63, height 1
SCREW-M3 [mm] "for M3"
  round 3.2 hole 3.2: 1(0,0)
SLP1006P2 [mm] "for Rclamp1561PQ"
  rect 0.65x0.65 smd mask+0.05: 1(-0.5,0) 2(0.5,0)
  body extent -0.5,-0.25 0.5,0.25, height 0.6
SLP1006P2T [mm] "Chip TVS Diode; Body 1.0 x 0.6 mm (LxW typ)"
  rect 0.55x0.6 smd mask+0.05: 1(-0.425,0) 2(0.425,0)
  silkscreen extent 0.9,-0.25 0.9,0.25, body extent -0.5,-0.3 0.5,0.3, height 0.8
SMA_END_LAUNCH_1.6MM_6.35MM [mm] "SMA end launch for 1.6mm PCB thickness; 6.35mm"
  rect 4.2x1.778 smd mask+0.05: 1(0,0)
  rect 4.2x2.667 hole 0.3 mask+0.05: 2(0,-3.495) 2(0,3.495)
  Top Layer pour cut-out: -2.15,2.165 2.15,2.165 2.149,-2.155 -2.154,-2.159
  MidLayer1 - GND pour cut-out: -2.129,2.135 -2.129,2.135 2.114,2.135
  MidLayer1 - GND pour cut-out: -2.15,2.166 2.15,2.166 2.149,-2.154 -2.154,-2.158
  MidLayer2 pour cut-out: -2.144,2.166 2.156,2.166 2.154,-2.155 -2.149,-2.158
  Bottom Layer pour cut-out: -2.148,2.166 2.152,2.166 2.151,-2.154 -2.152,-2.158
SOD523 [mm]
  rect 0.48x0.5 smd: 1(0,0) 2(1.32,0)
  silkscreen extent 1.78,-0.25 1.78,0.25
TACKLE_3*3MM [mm] "3*3*1.5"
  rect 1.2x0.5 smd: 1(-2.15,1.1) 1(2.15,1.1) 2(-2.15,-1.1) 2(2.15,-1.1)
  silkscreen extent -2.94,-1.54 2.9,1.54
"TCXO 2.0x1.6mm" [mm] "SMD 2.0x1.6mm for TCXO or VCTCXO"
  rect 0.6x0.8 smd mask+0.05: 1(-0.9,-0.6) 2(0.9,-0.6) 3(0.9,0.6) 4(-0.9,0.6)
  silkscreen extent -1.05,-1.45 -0.75,-1.15, body extent -1,-0.8 1,0.8, height 1
TSLP-7-1 [mm] "for BGB707L7ESD"
  rect 0.45x0.3 smd: 1(-0.95,0.5) 2(-0.95,0) 3(-0.95,-0.5) 4(0.95,-0.5) 5(0.95,0) 6(0.95,0.5)
  rect 1x1.3 smd: 7(0,0)
  silkscreen extent -1.21,-0.73 1.21,1.1
TSOT-23-5 [mm] "For RT9078"
  rect 0.85x0.4 smd mask+0.05: 1(-1.202,0.9) 2(-1.202,0) 3(-1.202,-0.9) 4(1.202,-0.9) 5(1.202,0.9)
  silkscreen extent -1.08,-0.85 0.15,1.77, body extent -0.7,-0.85 0.7,1.35, height 1.1
UDFN-6L_2X2mm [mm] "6 Leads, Body 2x2mm, pitch 0.65mm, UDFN-6L"
  rrect20% 1.05x0.3 smd paste+0 mask+0.05: 1(-0.85,0.65) 2(-0.85,0) 3(-0.85,-0.65) 4(0.85,-0.65) 5(0.85,0) 6(0.85,0.65)
  silkscreen extent -1.75,-0.98 1.61,1.13
UFL [mm] "SMD 2.0x1.6mm for Crystal,nx2016sa"
  rect 1.05x2.2 smd mask+0.05: 1(-1.475,0.763) 2(1.475,0.763)
  rect 1.05x1.05 smd mask+0.05: 3(0,-0.762)
  silkscreen extent -2.19,-1.47 2.19,2.05
UFQFPN32_5x5mm [mm] "QFN, 32-Leads, Body 5.1x5.1mm, Pitch 0.5mm, Thermal Pad 3.5x3.5mm, IPC High Density"
  oval 0.8x0.25 smd: 1(-2.4,1.75) 2(-2.4,1.25) 3(-2.4,0.75) 4(-2.4,0.25) 5(-2.4,-0.25) 6(-2.4,-0.75) 7(-2.4,-1.25) 8(-2.4,-1.75) 17(2.4,-1.75) 18(2.4,-1.25) 19(2.4,-0.75) 20(2.4,-0.25) 21(2.4,0.25) 22(2.4,0.75) 23(2.4,1.25) 24(2.4,1.75)
  oval 0.25x0.8 smd: 9(-1.75,-2.4) 10(-1.25,-2.4) 11(-0.75,-2.4) 12(-0.25,-2.4) 13(0.25,-2.4) 14(0.75,-2.4) 15(1.25,-2.4) 16(1.75,-2.4) 25(1.75,2.4) 26(1.25,2.4) 27(0.75,2.4) 28(0.25,2.4) 29(-0.25,2.4) 30(-0.75,2.4) 31(-1.25,2.4) 32(-1.75,2.4)
  rect 3.5x3.5 smd: 33(0,0)
  silkscreen extent -3.47,-2.7 2.7,2.7, body extent -2.55,-2.55 2.55,2.55, height 0.6
VQFN24_4X4MM [mm] "24 Leads, Body 4.0x4.0mm, Pitch 0.50mm, VQFN24"
  oval 0.8x0.3 smd mask+0.05: 1(-1.9,1.25) 2(-1.9,0.75) 3(-1.9,0.25) 4(-1.9,-0.25) 5(-1.9,-0.75) 6(-1.9,-1.25) 13(1.9,-1.25) 14(1.9,-0.75) 15(1.9,-0.25) 16(1.9,0.25) 17(1.9,0.75) 18(1.9,1.25)
  oval 0.3x0.8 smd mask+0.05: 7(-1.25,-1.9) 8(-0.75,-1.9) 9(-0.25,-1.9) 10(0.25,-1.9) 11(0.75,-1.9) 12(1.25,-1.9) 19(1.25,1.9) 20(0.75,1.9) 21(0.25,1.9) 22(-0.25,1.9) 23(-0.75,1.9) 24(-1.25,1.9)
  rrect5% 2.4x2.4 smd paste-2.5 mask+0.05: 25(0,0)
  Mechanical 15 keep-out lines w0.1: 2.5,-2.5 2.5,2.5 -2.5,2.5 -2.5,-2.5 2.5,-2.5
  silkscreen extent -2.5,-2.2 2.2,2.5, body extent -2,-2 2,2, height 1
vqfn24_4x4mm [mm] "24 Leads, Body 4.0x4.0mm, Pitch 0.50mm, VQFN24"
  oval 0.8x0.3 smd mask+0.05: 1(-1.9,1.25) 2(-1.9,0.75) 3(-1.9,0.25) 4(-1.9,-0.25) 5(-1.9,-0.75) 6(-1.9,-1.25) 13(1.9,-1.25) 14(1.9,-0.75) 15(1.9,-0.25) 16(1.9,0.25) 17(1.9,0.75) 18(1.9,1.25)
  oval 0.3x0.8 smd mask+0.05: 7(-1.25,-1.9) 8(-0.75,-1.9) 9(-0.25,-1.9) 10(0.25,-1.9) 11(0.75,-1.9) 12(1.25,-1.9) 19(1.25,1.9) 20(0.75,1.9) 21(0.25,1.9) 22(-0.25,1.9) 23(-0.75,1.9) 24(-1.25,1.9)
  rrect5% 2.4x2.4 smd paste-2.5 mask+0.05: 25(0,0)
  Mechanical 15 keep-out lines w0.1: -2.5,-2.5 -2.5,2.5 2.5,2.5 2.5,-2.5 -2.5,-2.5
  silkscreen extent -2.5,-2.2 2.2,2.5, body extent -2,-2 2,2, height 1
VQFN68_7X7MM [mm] "VQFN68 Leads, Body 7.0x7.0mm, Pitch 0.35mm"
  rrect25% 0.85x0.23 smd paste+0 mask+0.025: 1(-3.45,2.8) 2(-3.45,2.45) 3(-3.45,2.1) 4(-3.45,1.75) 5(-3.45,1.4) 6(-3.45,1.05) 7(-3.45,0.7) 8(-3.45,0.35) 9(-3.45,0) 10(-3.45,-0.35) 11(-3.45,-0.7) 12(-3.45,-1.05) 13(-3.45,-1.4) 14(-3.45,-1.75) 15(-3.45,-2.1) 16(-3.45,-2.45) 17(-3.45,-2.8) 35(3.45,-2.8) 36(3.45,-2.45) 37(3.45,-2.1) 38(3.45,-1.75) 39(3.45,-1.4) 40(3.45,-1.05) 41(3.45,-0.7) 42(3.45,-0.35) 43(3.45,0) 44(3.45,0.35) 45(3.45,0.7) 46(3.45,1.05) 47(3.45,1.4) 48(3.45,1.75) 49(3.45,2.1) 50(3.45,2.45) 51(3.45,2.8)
  rrect25% 0.23x0.85 smd paste+0 mask+0.025: 18(-2.8,-3.45) 19(-2.45,-3.45) 20(-2.1,-3.45) 21(-1.75,-3.45) 22(-1.4,-3.45) 23(-1.05,-3.45) 24(-0.7,-3.45) 25(-0.35,-3.45) 26(0,-3.45) 27(0.35,-3.45) 28(0.7,-3.45) 29(1.05,-3.45) 30(1.4,-3.45) 31(1.75,-3.45) 32(2.1,-3.45) 33(2.45,-3.45) 34(2.8,-3.45) 52(2.8,3.45) 53(2.45,3.45) 54(2.1,3.45) 55(1.75,3.45) 56(1.4,3.45) 57(1.05,3.45) 58(0.7,3.45) 59(0.35,3.45) 60(0,3.45) 61(-0.35,3.45) 62(-0.7,3.45) 63(-1.05,3.45) 64(-1.4,3.45) 65(-1.75,3.45) 66(-2.1,3.45) 67(-2.45,3.45) 68(-2.8,3.45)
  rrect2% 5.55x5.55 smd paste-6.6 mask+0.025: 69(0,0)
  silkscreen extent -4.05,-3.65 3.65,3.65, body extent -3.5,-3.5 3.5,3.5, height 0.9
XTAL_3215_SMD [mm] "XTAL SMD; Body 3.2x1.5 mm (LxW max)"
  rect 1x1.65 smd paste+0 mask+0.05: 1(-1.25,0) 2(1.25,0)
  body extent -1.6,-0.75 1.6,0.75, height 0.9

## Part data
433MHz 490MHz 920MHz Other R1 R2 R3 R4 R5 R6 R7 R8 R9 R10 R11 R12 R13 R14 R15 R16 R17 R18 R19 R20 R21 R24 R25 R26 R27 R28 R29 R30 R31 R32 R33 R34 R35 R36 R37 R38 R41 R42 R44 R45 R46 R48 R49 R50 R51 R52 R53 R54 R55 R56 R57 R58 R59 R60 R61 R62 R63 R64 R65 SX1302 SX1303: "Resistor SMD - IEC symbol version"
BOOT NRST: library part SW-SPST, "SPST, N.O. - Tactile Switch"
C1 C2 C3 C4 C5 C6 C7 C8 C9 C10 C11 C12 C13 C14 C16 C17 C18 C19 C20 C21 C22 C23 C24 C25 C26 C27 C28 C29 C30 C31 C32 C33 C34 C35 C36 C37 C38 C39 C40 C41 C42 C43 C44 C45 C46 C47 C48 C49 C50 C51 C52 C53 C54 C55 C56 C57 C58 C59 C60 C61 C62 C64 C65 C66 C67 C68 C69 C70 C71 C72 C73 C74 C75: "Capacitor SMD"
C15: "Capacitor SMD", DC Voltage=16V
D1 D2 D3 D11: library part RClamp0531T, "Ultra Low Capacitance 1-line ESD Protection"
D4 D6: "Unidirectional,Ultra Low Capacitance 1-line ESD Protection"
D5: "Schottky Diode", MPN=BAT54XV2T1G
"Fiducial Mark1" "Logo LoRa 1" "Logo Semtech 2" SCREW-1 SCREW-2 SCREW-3: library part Logo, "Schematic symbol for Logo"
LED_RX LED_TX: library part LED, "LED"
MCU_H1: "Header, 5-Pin"
MCU_UART_RX MCU_UART_TX RADIO_CTRL_0 RADIO_CTRL_4 RADIO_CTRL_5 RADIO_CTRL_6 RADIO_CTRL_7 RADIO_CTRL_8 RADIO_CTRL_10 RADIO_CTRL_11 SX1_DIO2 SX1_DIO3 SX1302_LNA_REG_EN TP_GPIO0 TP_GPIO1 TP_GPIO3 TP_GPIO5 TP_GPIO6 TP_GPIO9 VCCCORE12 VCCIO33 VDD_RF_1250 VDD_RF_LNA: library part test_pin
Q1: library part Xtal, "Crystal oscillator"
R22 R23 R39 R40 R43: library part Res, "SMD Resistor"
RFIO1: "SMA Straight Connector"
RT1 RT4: library part RT9078, "LDO"
RT2: "DCDC"
SPI_H1: "Header, 12-Pin, Dual row"
U1: library part SX1302, "SX1302 - Base Band Processor for Data Concentrator for Long Range Communication Network;"
U2 U6: "SX1250 - Ultra low power RF Front-End"
U3: library part "MXD8621C Switch", "MXD8621C Switch"
U4: "Ultra-low-power Arm? Cortex?-M4 32-bit MCU+FPU, 100DMIPS, up to 128KB Flash, 40KB SRAM, analog, ext. SMPS"
U5: library part STTS751, "2.25 V low-voltage local digital temperature sensor"
U7 U8 U9: "SAW Filter - Bandpass - TEMEX type"
U10: "LAN,Adjustable gain", Frequency (f)="10MHz - 1000MHz", Manufacturer=Infineon
U11: library part SX126x, "SX1261/2 - Ultra low power RF transceiver"
UFL1: "UFL connector"
USB_DC_IN1: "USB 2.0 SMT, Type A, Receptacle, 4 Position"

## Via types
v1: diameter 0.5, hole 0.25, Top Layer to Bottom Layer, tented both sides, 1086 vias
v2: diameter 0.6, hole 0.3, Top Layer to Bottom Layer, tented top, 49 vias
v3: diameter 0.5, hole 0.25, Top Layer to Bottom Layer, 16 vias
v4: diameter 0.5, hole 0.2, Top Layer to Bottom Layer, 9 vias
